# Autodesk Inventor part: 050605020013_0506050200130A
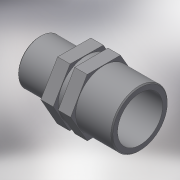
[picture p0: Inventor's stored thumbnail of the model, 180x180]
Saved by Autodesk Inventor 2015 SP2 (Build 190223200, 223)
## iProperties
Created: 2017-05
Part Number: 050605020013_0506050200130A
Material: Generic
Description: PLASSON REDUCING NIPPLE 2"-1.1/4"
Document SubType Name: Modeling
Designer: KIM
Density: 1 g/cm^3
Appearance: Default
Author: KIM
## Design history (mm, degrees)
derived "050605.ipt"
feature "Solid1::050605.ipt"
tag "TaggingFeature1"
body "Solid1"
other parameters: "d0" = 63, "d1" = 59.614, "d5" = 25, "d6" = 6.3, "d8" = 0.63, "d12" = 0, "d14" = 41.91, "d15" = 33.528, "d16" = 47.6912, "d17" = 21, "d18" = 3.15, "d19" = 63, "d21" = 0, "H_" = 63, "R_" = 59.614, "E_" = 63, "l_" = 25, "R_1" = 41.91, "l_1" = 21
